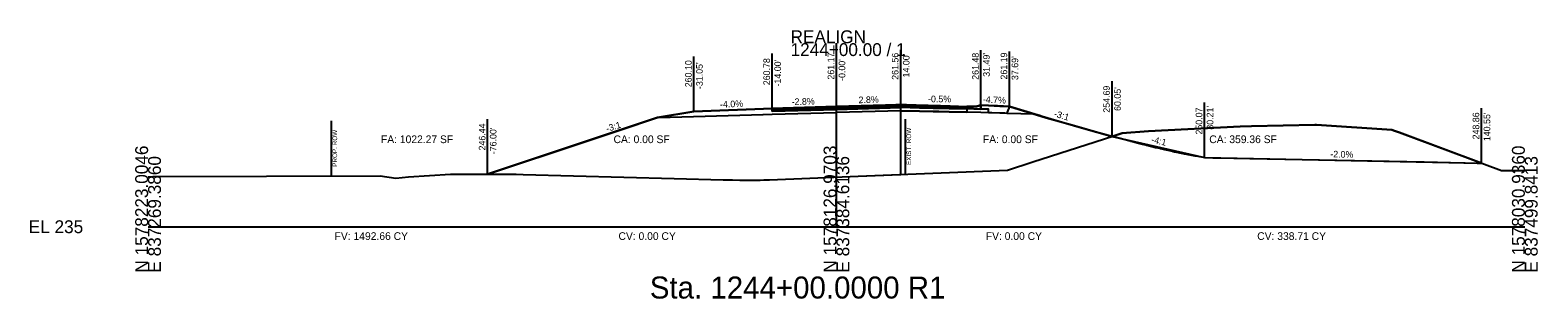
# Model space of a CAD drawing. Extents: x -26 to 6303, y -16 to 9563.
# Drawn here: x 1974.3 to 2302.8, y 4984.3 to 5042.8 of the extents above; entities that cross this region are included whole.
import ezdxf

# ---------------------------------------------------------------- set-up
doc = ezdxf.new("R2010")
doc.units = 0
for name, color, linetype in [('ASPHALT_19MM1', 7, 'Continuous'), ('ASPHALT_9_5MM1', 7, 'Continuous'), ('CONST_DCH', 7, 'Continuous'), ('CONST_LV3', 7, 'Continuous'), ('Default', 7, 'Continuous'), ('Draft_XS_Grid', 7, 'Continuous'), ('Draft_XS_Text', 7, 'Continuous'), ('DTM_P_FINISHED_GRADE', 7, 'Continuous'), ('DTM_P_FINISHED_GRADE2', 7, 'Continuous'), ('DTM_TEMP_DROP', 7, 'Continuous'), ('DTM_X_GROUND', 7, 'Continuous'), ('TRANS_EOP_PAVED', 7, 'Continuous'), ('TRANS_PAVED_SHOULDERS', 7, 'Continuous'), ('XS_CELL', 7, 'Continuous'), ('XS_M_SHAPES_EARTHWORK', 7, 'Continuous'), ('XS_P_ASPHALT', 7, 'Continuous'), ('XS_P_CONCRETE', 7, 'Continuous'), ('XS_P_GROUND', 7, 'Continuous'), ('XS_P_ROW', 7, 'Continuous'), ('XS_P_SHOULDER', 7, 'Continuous'), ('XS_P_SUBGRADE_GRANULAR', 7, 'Continuous'), ('XS_P_SUBGRADE_GRANULAR_B', 7, 'Continuous'), ('XS_P_TX_CLEARZONE', 7, 'Continuous'), ('XS_P_TX_FS_BS', 7, 'Continuous'), ('XS_SHEET_EW_TX_AREA', 7, 'Continuous'), ('XS_SHEET_EW_TX_VOLUME', 7, 'Continuous'), ('XS_X_ROW', 7, 'Continuous')]:
    doc.layers.add(name, color=color, linetype=linetype)

msp = doc.modelspace()

# ---------------------------------------------------------------- linework, layer by layer
at = {"layer": 'ASPHALT_19MM1'}
for points in [[(2136, 5025.45), (2136, 5025.17), (2150, 5025.57), (2150, 5025.57), (2164, 5025.96), (2164, 5025.96), (2164, 5026.23), (2164, 5026.23), (2164, 5026.23), (2150, 5025.84), (2150, 5025.84), (2136, 5025.45), (2136, 5025.45)], [(2174.55, 5025.99), (2178.43, 5025.9), (2178.43, 5025.63), (2174.55, 5025.72), (2172.28, 5025.77), (2171.11, 5025.8), (2168.07, 5025.86), (2164, 5025.96), (2164, 5025.96), (2164, 5026.23), (2164, 5026.23), (2168.07, 5026.14), (2171.11, 5026.07), (2172.28, 5026.04), (2174.55, 5025.99)]]:
    msp.add_lwpolyline(points, dxfattribs=at)
at = {"layer": 'ASPHALT_9_5MM1'}
for points in [[(2136, 5025.78), (2136, 5025.65), (2150, 5026.05), (2150, 5026.05), (2164, 5026.44), (2164, 5026.44), (2164, 5026.56), (2164, 5026.56), (2164, 5026.56), (2150, 5026.17), (2150, 5026.17), (2136, 5025.78), (2136, 5025.78)], [(2174.55, 5026.32), (2178.43, 5026.23), (2178.43, 5026.1), (2174.55, 5026.2), (2172.28, 5026.25), (2171.11, 5026.28), (2168.07, 5026.34), (2164, 5026.44), (2164, 5026.44), (2164, 5026.56), (2164, 5026.56), (2168.07, 5026.47), (2171.11, 5026.4), (2172.28, 5026.37), (2174.55, 5026.32)]]:
    msp.add_lwpolyline(points, dxfattribs=at)
at = {"layer": 'CONST_LV3'}
for points in [[(2172.7, 5026.37), (2167.36, 5026.49), (2167.36, 5026.49), (2165.26, 5026.53), (2165.26, 5026.53), (2165.26, 5026.53), (2164, 5026.56), (2163.57, 5026.55), (2163.57, 5026.55), (2163.29, 5026.54), (2163.29, 5026.54), (2162.96, 5026.53), (2162.96, 5026.53), (2160.66, 5026.47), (2160.66, 5026.47), (2160.66, 5026.47), (2150, 5026.17)], [(2174.55, 5026.32), (2178.43, 5026.23), (2178.43, 5024.96), (2174.55, 5025.05), (2172.28, 5025.1), (2171.11, 5025.13), (2168.07, 5025.2), (2164, 5025.29), (2164, 5025.29), (2164, 5026.56), (2164, 5026.56), (2168.07, 5026.47), (2171.11, 5026.4), (2172.28, 5026.37), (2174.55, 5026.32)], [(2181.44, 5026.48), (2181.44, 5025.65), (2181.36, 5025.65), (2178.4, 5025.73), (2178.4, 5026.23), (2180.61, 5026.17), (2180.61, 5026.25), (2181.36, 5026.46), (2181.44, 5026.48)], [(2187.66, 5026.19), (2186.94, 5026.22), (2186.37, 5026.25), (2186.08, 5026.26), (2185.98, 5026.27), (2185.73, 5026.28), (2185.61, 5026.29), (2185.26, 5026.3), (2185.02, 5026.32), (2183.77, 5026.37), (2181.44, 5026.48)], [(2230.21, 5015.07), (2229.19, 5015.23), (2229.17, 5015.23), (2228.38, 5015.36), (2228.38, 5015.36), (2228.37, 5015.36), (2228.37, 5015.36), (2228.37, 5015.36), (2228.37, 5015.36), (2228.35, 5015.37), (2228.34, 5015.37), (2228.31, 5015.37), (2228.3, 5015.37), (2228.23, 5015.39), (2228.14, 5015.4), (2226.7, 5015.67), (2226.62, 5015.68), (2225.97, 5015.81), (2225.97, 5015.81), (2225.95, 5015.81), (2225.95, 5015.81), (2225.93, 5015.82), (2225.91, 5015.82), (2225.82, 5015.84), (2225.52, 5015.89), (2223.78, 5016.26), (2223.7, 5016.28), (2223.41, 5016.34), (2223.41, 5016.34), (2223.4, 5016.34), (2223.4, 5016.35), (2223.39, 5016.35), (2223.38, 5016.35), (2223.35, 5016.36), (2223.33, 5016.36), (2223.24, 5016.38), (2222.95, 5016.44), (2222, 5016.66), (2221.99, 5016.66), (2221.96, 5016.67), (2221.96, 5016.67), (2221.94, 5016.68), (2221.58, 5016.75), (2220.68, 5016.97), (2220.67, 5016.97), (2220.65, 5016.98), (2220.65, 5016.98), (2220.64, 5016.98), (2220.64, 5016.98), (2220.64, 5016.98), (2220.59, 5016.99), (2220.48, 5017.02), (2220.48, 5017.02), (2220.46, 5017.02), (2219.49, 5017.23), (2217.65, 5017.71), (2217.64, 5017.71), (2217.62, 5017.71), (2217.62, 5017.71), (2217.61, 5017.72), (2217.6, 5017.72), (2217.6, 5017.72), (2217.52, 5017.74), (2217.41, 5017.77), (2217.08, 5017.84), (2216.66, 5017.95), (2215.56, 5018.22), (2214.31, 5018.56), (2214.28, 5018.56), (2214.25, 5018.57), (2214.24, 5018.57), (2214.22, 5018.58), (2214.22, 5018.58), (2214.21, 5018.58), (2214.1, 5018.61), (2213.99, 5018.64), (2213.4, 5018.78), (2212.9, 5018.92), (2211.51, 5019.28), (2210.51, 5019.56), (2210.46, 5019.57), (2210.43, 5019.58), (2210.39, 5019.59), (2210.37, 5019.6), (2210.36, 5019.6), (2210.36, 5019.6), (2210.2, 5019.64), (2210.1, 5019.67), (2209.21, 5019.91), (2208.71, 5020.05), (2206.92, 5020.53), (2206.11, 5020.77), (2206.02, 5020.8), (2205.99, 5020.81), (2205.92, 5020.82), (2205.89, 5020.83), (2205.88, 5020.84), (2205.88, 5020.84), (2205.66, 5020.9), (2205.58, 5020.92), (2204.28, 5021.28), (2203.85, 5021.41), (2201.48, 5022.08), (2200.88, 5022.26), (2200.73, 5022.3), (2200.7, 5022.31), (2200.59, 5022.34), (2200.56, 5022.35), (2200.54, 5022.36), (2200.54, 5022.36), (2200.51, 5022.37), (2200.51, 5022.37), (2200.23, 5022.45), (2200.17, 5022.46), (2198.32, 5023), (2198.01, 5023.09), (2194.81, 5024.03), (2194.48, 5024.14), (2194.24, 5024.21), (2194.22, 5024.21), (2193.99, 5024.28), (2193.97, 5024.29), (2193.94, 5024.3), (2193.93, 5024.3), (2193.55, 5024.41), (2193.52, 5024.42), (2190.87, 5025.21), (2190.76, 5025.25), (2187.66, 5026.19), (2186.94, 5026.22), (2186.37, 5026.25), (2186.08, 5026.26), (2185.98, 5026.27), (2185.73, 5026.28), (2185.61, 5026.29), (2185.26, 5026.3), (2185.02, 5026.32), (2183.77, 5026.37), (2181.44, 5026.48)], [(2210.05, 5019.69), (2205.88, 5020.84), (2203.88, 5021.4), (2200.54, 5022.36), (2195.72, 5023.76), (2193.97, 5024.29), (2187.69, 5026.19), (2186.89, 5026.23), (2185.61, 5026.29), (2183.13, 5026.41), (2181.49, 5026.48)], [(2183.16, 5024.83), (2183.16, 5025.6), (2181.49, 5025.65)]]:
    msp.add_lwpolyline(points, dxfattribs=at)
at = {"layer": 'Default'}
msp.add_lwpolyline([(2172.7, 5026.37), (2174.56, 5026.32), (2178.4, 5026.23)], dxfattribs=at)
at = {"layer": 'DTM_P_FINISHED_GRADE'}
msp.add_lwpolyline([(2164, 5026.56), (2164, 5026.56), (2168.07, 5026.47), (2171.11, 5026.4), (2172.28, 5026.37), (2174.55, 5026.32), (2178.43, 5026.23)], dxfattribs=at)
at = {"layer": 'DTM_P_FINISHED_GRADE2'}
msp.add_lwpolyline([(2074, 5011.44), (2095.42, 5018.58), (2102.83, 5021.05), (2111, 5023.77), (2118.95, 5025.1), (2136, 5025.78), (2150, 5026.17), (2164, 5026.56), (2168.07, 5026.47), (2171.11, 5026.4), (2172.28, 5026.38), (2174.79, 5026.32), (2178.43, 5026.23), (2179.71, 5026.2), (2180.65, 5026.17), (2180.65, 5026.21), (2180.65, 5026.25), (2181.03, 5026.36), (2181.49, 5026.48), (2183.13, 5026.41), (2185.61, 5026.29), (2187.69, 5026.19), (2195.72, 5023.76), (2199.4, 5022.7), (2203.88, 5021.4), (2210.05, 5019.69)], dxfattribs=at)
at = {"layer": 'DTM_X_GROUND'}
msp.add_lwpolyline([(2000, 5010.91), (2001.07, 5010.92), (2050.58, 5011.11), (2053.97, 5010.59), (2056.74, 5010.89), (2065.87, 5011.46), (2072.6, 5011.45), (2080.18, 5011.42), (2081.73, 5011.41), (2114.61, 5010.53), (2125.29, 5010.24), (2127.33, 5010.2), (2128.96, 5010.16), (2130.85, 5010.16), (2132.11, 5010.17), (2133.35, 5010.18), (2134.18, 5010.19), (2135.45, 5010.25), (2154.7, 5011.04), (2187.25, 5012.33), (2192.83, 5014.11), (2212.25, 5020.4), (2217.97, 5020.85), (2237.97, 5021.87), (2240.44, 5021.94), (2254.21, 5022.21), (2254.41, 5022.21), (2254.6, 5022.2), (2271, 5021.13), (2271.61, 5020.9), (2272.68, 5020.5), (2294.91, 5012.24), (2296.98, 5012.23), (2300, 5012.23)], dxfattribs=at)
at = {"layer": 'TRANS_PAVED_SHOULDERS'}
for points in [[(2136, 5025.65), (2136, 5025.45), (2150, 5025.84), (2150, 5025.84), (2164, 5026.23), (2164, 5026.23), (2164, 5026.44), (2164, 5026.44), (2164, 5026.44), (2150, 5026.05), (2150, 5026.05), (2136, 5025.65), (2136, 5025.65)], [(2174.55, 5026.2), (2178.43, 5026.1), (2178.43, 5025.9), (2174.55, 5025.99), (2172.28, 5026.04), (2171.11, 5026.07), (2168.07, 5026.14), (2164, 5026.23), (2164, 5026.23), (2164, 5026.44), (2164, 5026.44), (2168.07, 5026.34), (2171.11, 5026.28), (2172.28, 5026.25), (2174.55, 5026.2)]]:
    msp.add_lwpolyline(points, dxfattribs=at)
at = {"layer": 'XS_CELL'}
for p, q in [((2150, 5000), (2150, 5040)), ((2000, 5000), (2150, 5000)), ((2150, 5000), (2300, 5000))]:
    msp.add_line(p, q, dxfattribs=at)
at = {"layer": 'XS_M_SHAPES_EARTHWORK'}
msp.add_lwpolyline([(2074, 5011.44), (2080.18, 5011.42), (2081.73, 5011.41), (2114.61, 5010.53), (2125.29, 5010.24), (2127.33, 5010.2), (2128.96, 5010.16), (2130.85, 5010.16), (2132.11, 5010.17), (2133.35, 5010.18), (2134.18, 5010.19), (2135.45, 5010.25), (2154.7, 5011.04), (2164, 5011.41), (2164, 5025.96), (2150, 5025.57), (2136, 5025.17), (2136, 5025.45), (2136, 5025.65), (2136, 5025.78), (2118.95, 5025.1), (2111.26, 5023.82), (2111, 5023.77)], close=True, dxfattribs=at)
at = {"layer": 'XS_P_ASPHALT'}
msp.add_lwpolyline([(2164, 5026.56), (2164, 5026.56), (2168.07, 5026.47), (2171.11, 5026.4), (2172.28, 5026.37), (2174.55, 5026.32), (2178.43, 5026.23)], dxfattribs=at)
at = {"layer": 'XS_P_CONCRETE'}
msp.add_lwpolyline([(2178.43, 5026.23), (2178.43, 5025.73), (2181.49, 5025.65), (2181.49, 5026.48), (2180.65, 5026.25), (2180.65, 5026.17), (2178.43, 5026.23)], dxfattribs=at)
at = {"layer": 'XS_P_GROUND'}
for points in [[(2118.95, 5025.1), (2111, 5023.77), (2074, 5011.44)], [(2230.21, 5015.07), (2229.19, 5015.23), (2229.17, 5015.23), (2228.38, 5015.36), (2228.38, 5015.36), (2228.37, 5015.36), (2228.37, 5015.36), (2228.37, 5015.36), (2228.37, 5015.36), (2228.35, 5015.37), (2228.34, 5015.37), (2228.31, 5015.37), (2228.3, 5015.37), (2228.23, 5015.39), (2228.14, 5015.4), (2226.7, 5015.67), (2226.62, 5015.68), (2225.97, 5015.81), (2225.97, 5015.81), (2225.95, 5015.81), (2225.95, 5015.81), (2225.93, 5015.82), (2225.91, 5015.82), (2225.82, 5015.84), (2225.52, 5015.89), (2223.78, 5016.26), (2223.7, 5016.28), (2223.41, 5016.34), (2223.41, 5016.34), (2223.4, 5016.34), (2223.4, 5016.35), (2223.39, 5016.35), (2223.38, 5016.35), (2223.35, 5016.36), (2223.33, 5016.36), (2223.24, 5016.38), (2222.95, 5016.44), (2222, 5016.66), (2221.99, 5016.66), (2221.96, 5016.67), (2221.96, 5016.67), (2221.94, 5016.68), (2221.58, 5016.75), (2220.68, 5016.97), (2220.67, 5016.97), (2220.65, 5016.98), (2220.65, 5016.98), (2220.64, 5016.98), (2220.64, 5016.98), (2220.64, 5016.98), (2220.59, 5016.99), (2220.48, 5017.02), (2220.48, 5017.02), (2220.46, 5017.02), (2219.49, 5017.23), (2217.65, 5017.71), (2217.64, 5017.71), (2217.62, 5017.71), (2217.62, 5017.71), (2217.61, 5017.72), (2217.6, 5017.72), (2217.6, 5017.72), (2217.52, 5017.74), (2217.41, 5017.77), (2217.08, 5017.84), (2216.66, 5017.95), (2215.56, 5018.22), (2214.31, 5018.56), (2214.28, 5018.56), (2214.25, 5018.57), (2214.24, 5018.57), (2214.22, 5018.58), (2214.22, 5018.58), (2214.21, 5018.58), (2214.1, 5018.61), (2213.99, 5018.64), (2213.4, 5018.78), (2212.9, 5018.92), (2211.51, 5019.28), (2210.51, 5019.56), (2210.46, 5019.57), (2210.43, 5019.58), (2210.39, 5019.59), (2210.37, 5019.6), (2210.36, 5019.6), (2210.36, 5019.6), (2210.2, 5019.64), (2210.1, 5019.67), (2209.21, 5019.91), (2208.71, 5020.05), (2206.92, 5020.53), (2206.11, 5020.77), (2206.02, 5020.8), (2205.99, 5020.81), (2205.92, 5020.82), (2205.89, 5020.83), (2205.88, 5020.84), (2205.88, 5020.84), (2205.66, 5020.9), (2205.58, 5020.92), (2204.28, 5021.28), (2203.85, 5021.41), (2201.48, 5022.08), (2200.88, 5022.26), (2200.73, 5022.3), (2200.7, 5022.31), (2200.59, 5022.34), (2200.56, 5022.35), (2200.54, 5022.36), (2200.54, 5022.36), (2200.51, 5022.37), (2200.51, 5022.37), (2200.23, 5022.45), (2200.17, 5022.46), (2198.32, 5023), (2198.01, 5023.09), (2194.81, 5024.03), (2194.48, 5024.14), (2194.24, 5024.21), (2194.22, 5024.21), (2193.99, 5024.28), (2193.97, 5024.29), (2193.94, 5024.3), (2193.93, 5024.3), (2193.55, 5024.41), (2193.52, 5024.42), (2190.87, 5025.21), (2190.76, 5025.25), (2187.66, 5026.19)], [(2210.05, 5019.69), (2205.88, 5020.84), (2203.88, 5021.4), (2200.54, 5022.36), (2195.72, 5023.76), (2193.97, 5024.29), (2187.69, 5026.19)], [(2230.21, 5015.07), (2232.04, 5015.03), (2232.04, 5015.03), (2232.04, 5015.03), (2232.04, 5015.03), (2232.31, 5015.02), (2232.31, 5015.02), (2232.53, 5015.02), (2232.53, 5015.02), (2233.01, 5015.01), (2233.01, 5015.01), (2233.01, 5015.01), (2233.04, 5015.01), (2233.14, 5015.01), (2233.14, 5015.01), (2240.07, 5014.87), (2240.07, 5014.87)], [(2240.07, 5014.87), (2278.08, 5014.11), (2289.62, 5013.88), (2290.55, 5013.86)]]:
    msp.add_lwpolyline(points, dxfattribs=at)
at = {"layer": 'XS_P_ROW'}
msp.add_line((2040, 5011.07), (2040, 5023.07), dxfattribs=at)
at = {"layer": 'XS_P_SHOULDER'}
for points in [[(2118.95, 5025.1), (2118.95, 5025.1), (2136, 5025.78)], [(2187.69, 5026.19), (2186.89, 5026.23), (2185.61, 5026.29), (2183.13, 5026.41), (2181.49, 5026.48)]]:
    msp.add_lwpolyline(points, dxfattribs=at)
at = {"layer": 'XS_P_SUBGRADE_GRANULAR'}
for points in [[(2111.26, 5023.82), (2134, 5024.45), (2134, 5024.45), (2136, 5024.51), (2136, 5024.51)], [(2136, 5024.51), (2150, 5024.9), (2150, 5024.9)], [(2164, 5025.29), (2164, 5025.29), (2150, 5024.9)], [(2164, 5025.29), (2164, 5025.29), (2168.07, 5025.2), (2171.11, 5025.13), (2172.28, 5025.1), (2174.55, 5025.05), (2178.43, 5024.96)], [(2181.49, 5024.88), (2178.43, 5024.96)], [(2183.16, 5024.83), (2181.49, 5024.88)]]:
    msp.add_lwpolyline(points, dxfattribs=at)
at = {"layer": 'XS_P_SUBGRADE_GRANULAR_B'}
for points in [[(2187.11, 5024.71), (2186.67, 5024.73), (2185.61, 5024.76), (2183.88, 5024.81), (2183.16, 5024.83)], [(2187.69, 5026.19), (2187.21, 5024.97), (2187.11, 5024.71)], [(2193.21, 5024.52), (2190.2, 5024.62), (2187.11, 5024.71)]]:
    msp.add_lwpolyline(points, dxfattribs=at)
at = {"layer": 'XS_P_TX_CLEARZONE'}
for p, q in [((2118.95, 5025.1), (2118.95, 5037.1)), ((2136, 5025.78), (2136, 5037.78)), ((2150, 5026.17), (2150, 5038.17)), ((2164, 5026.56), (2164, 5038.56)), ((2181.49, 5026.48), (2181.49, 5038.48)), ((2187.69, 5026.19), (2187.69, 5038.19)), ((2210.05, 5019.69), (2210.05, 5031.69)), ((2230.21, 5015.07), (2230.21, 5027.07)), ((2074, 5011.44), (2074, 5023.44)), ((2290.55, 5013.86), (2290.55, 5025.86))]:
    msp.add_line(p, q, dxfattribs=at)
at = {"layer": 'XS_P_TX_FS_BS'}
for p, q in [((2210.05, 5019.69), (2230.21, 5015.07)), ((2230.21, 5015.07), (2290.55, 5013.86))]:
    msp.add_line(p, q, dxfattribs=at)
msp.add_lwpolyline([(2290.55, 5013.86), (2272.68, 5020.5), (2271.61, 5020.9), (2271, 5021.13), (2254.6, 5022.2), (2254.41, 5022.21), (2254.21, 5022.21), (2240.44, 5021.94), (2237.97, 5021.87), (2217.97, 5020.85), (2212.25, 5020.4), (2210.05, 5019.69)], dxfattribs=at)
at = {"layer": 'XS_X_ROW'}
msp.add_line((2165.07, 5011.45), (2165.07, 5023.45), dxfattribs=at)

# ---------------------------------------------------------------- texts
at = {"layer": 'CONST_DCH'}
for p in [(2163.92, 5026.44), (2135.92, 5025.66), (2149.92, 5026.05), (2230.13, 5014.95)]:
    msp.add_text('X', height=0.24, dxfattribs=at).set_placement(p)
at = {"layer": 'Draft_XS_Grid'}
msp.add_text('-', height=0.0001, dxfattribs=at).set_placement((2000, 5000))
at = {"layer": 'Draft_XS_Text'}
msp.add_text('Sta. 1244+00.0000 R1', height=4.8, dxfattribs=at).set_placement((2109.33, 4984.35))
at = {"layer": 'DTM_TEMP_DROP'}
for p in [(2187.58, 5026.07), (2209.97, 5019.57), (2073.92, 5011.32)]:
    msp.add_text('X', height=0.24, dxfattribs=at).set_placement(p)
at = {"layer": 'TRANS_EOP_PAVED'}
for p in [(2209.97, 5019.57), (2073.92, 5011.32)]:
    msp.add_text('X', height=0.24, dxfattribs=at).set_placement(p)
at = {"layer": 'XS_CELL'}
for s, p in [('1244+00.00 / 1', (2140, 5037.2)), ('REALIGN', (2140, 5040)), ('EL 235', (1974, 4998.6))]:
    msp.add_text(s, height=2.8, dxfattribs=at).set_placement(p)
for s, p in [('N 1578223.0046', (2000, 4990)), ('N 1578126.9703', (2150, 4990)), ('N 1578030.9360', (2300, 4990)), ('E 837269.3860', (2002.8, 4990)), ('E 837384.6136', (2152.8, 4990)), ('E 837499.8413', (2302.8, 4990))]:
    msp.add_text(s, height=2.8, rotation=90, dxfattribs=at).set_placement(p)
at = {"layer": 'XS_P_ASPHALT'}
for p in [(2230.13, 5014.95), (2290.47, 5013.74)]:
    msp.add_text('X', height=0.24, dxfattribs=at).set_placement(p)
at = {"layer": 'XS_P_ROW'}
msp.add_text('PROP. ROW', height=1, rotation=90, dxfattribs=at).set_placement((2041.2, 5013.07))
at = {"layer": 'XS_P_SUBGRADE_GRANULAR'}
for p in [(2181.41, 5026.36), (2118.87, 5024.98), (2187.61, 5026.07)]:
    msp.add_text('X', height=0.24, dxfattribs=at).set_placement(p)
at = {"layer": 'XS_P_TX_CLEARZONE'}
for s, p in [('260.78', (2135.52, 5030.84)), ('261.17', (2149.52, 5032.07)), ("-0.00'", (2151.92, 5031.78)), ('261.56', (2163.52, 5032.02)), ("14.00'", (2165.92, 5032.53)), ('261.48', (2181.01, 5032.02)), ("31.49'", (2183.41, 5032.68)), ('261.19', (2187.21, 5032.08)), ("37.69'", (2189.61, 5031.96)), ('260.10', (2118.47, 5030.4)), ("-31.05'", (2120.87, 5030)), ("-14.00'", (2137.92, 5030.57)), ('254.69', (2209.57, 5024.85)), ("60.05'", (2211.97, 5025.23)), ('250.07', (2229.73, 5020.09)), ("80.21'", (2232.13, 5021.15)), ('248.86', (2290.07, 5019.03)), ("140.55'", (2292.47, 5018.65)), ('246.44', (2073.52, 5016.62)), ("-76.00'", (2075.92, 5015.8))]:
    msp.add_text(s, height=1.44, rotation=90, dxfattribs=at).set_placement(p)
at = {"layer": 'XS_P_TX_FS_BS'}
for s, rotation, p in [('-4.0%', 2.2906, (2124.66, 5025.93)), ('-2.8%', 1.6039, (2140.25, 5026.5)), ('2.8%', 1.6039, (2154.84, 5026.91)), ('-0.5%', 359.7276, (2169.96, 5027.13)), ('-4.7%', 357.3107, (2181.87, 5027.06)), ('-3:1', 343.7928, (2197.29, 5024.02)), ('-3:1', 16.9013, (2100.02, 5020.64)), ('-4:1', 347.0864, (2218.5, 5018.37)), ('-2.0%', 358.8542, (2257.6, 5015.12))]:
    msp.add_text(s, height=1.44, rotation=rotation, dxfattribs=at).set_placement(p)
at = {"layer": 'XS_SHEET_EW_TX_AREA'}
for s, p in [('FA: 1022.27 SF', (2050.75, 5018.22)), ('CA: 0.00 SF', (2101.43, 5018.22)), ('FA: 0.00 SF', (2181.92, 5018.22)), ('CA: 359.36 SF', (2231.24, 5018.22))]:
    msp.add_text(s, height=1.68, dxfattribs=at).set_placement(p)
at = {"layer": 'XS_SHEET_EW_TX_VOLUME'}
for s, p in [('FV: 1492.66 CY', (2040.65, 4997.12)), ('CV: 0.00 CY', (2102.51, 4997.12)), ('FV: 0.00 CY', (2182.55, 4997.12)), ('CV: 338.71 CY', (2241.69, 4997.12))]:
    msp.add_text(s, height=1.68, dxfattribs=at).set_placement(p)
at = {"layer": 'XS_X_ROW'}
msp.add_text('EXIST. ROW', height=1, rotation=90, dxfattribs=at).set_placement((2166.27, 5013.45))

doc.saveas('drawing.dxf')
